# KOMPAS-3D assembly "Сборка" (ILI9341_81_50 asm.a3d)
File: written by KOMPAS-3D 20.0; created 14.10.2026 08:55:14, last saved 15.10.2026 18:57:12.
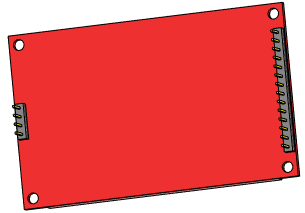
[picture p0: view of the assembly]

Document properties: Полное имя файла: D:\RicWork\Project-EPS32\box_compas\монитор\ILI9341_81_50 asm.a3d

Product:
- Part/product: Сборка
    Масса: 0.125759
  - Component [detail]: Деталь  | Масса: 0.123412; source file: ILI9341_81х50.m3d
  - Component [detail]: Деталь  | Масса: 0.00182492; source file: ..\разъемы\pls_14.m3d
  - Component [detail]: Деталь  | Масса: 0.000521406; source file: ..\разъемы\pls_4.m3d

Referenced files in D:\RicWork\Project-EPS32\box_compas\монитор\: ILI9341_81х50.m3d
Referenced files in D:\RicWork\Project-EPS32\box_compas\разъемы\: pls_14.m3d, pls_4.m3d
